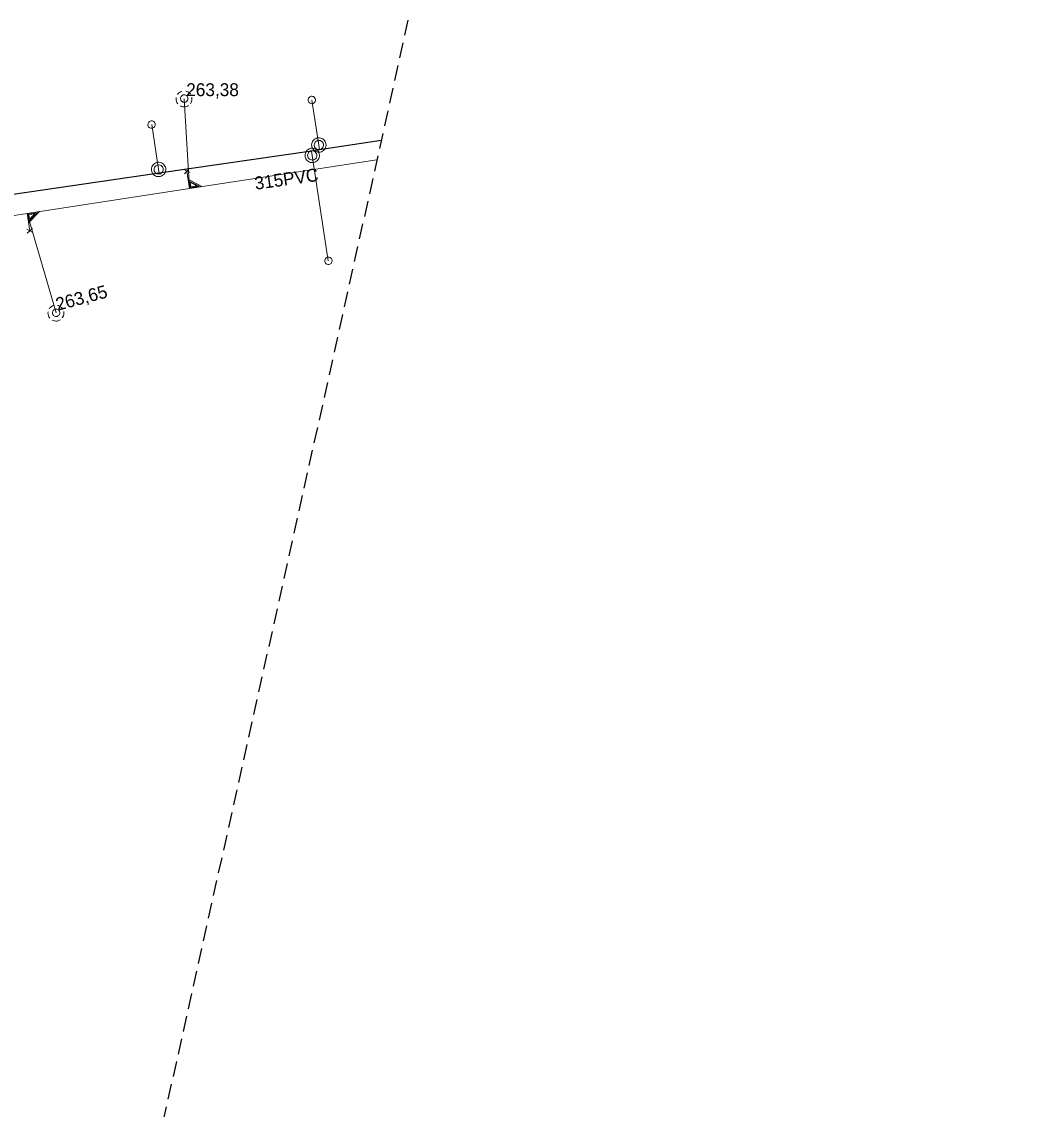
# Model space of a CAD drawing. Extents: x -732096 to -731933, y -1048703 to -1047964.
# Drawn here: x -732030.5 to -731968.4, y -1048368.5 to -1048301 of the extents above; entities that cross this region are included whole.
import ezdxf

# ---------------------------------------------------------------- set-up
doc = ezdxf.new("R2010")
doc.units = 0
doc.header["$LTSCALE"] = 0.32
doc.linetypes.add('MEDIUM_DASHED', pattern=[4.5, 3, -1.5])
doc.layers.add('1', color=7, linetype='Continuous')
for name, color, linetype, lineweight in [('18', 7, 'Continuous', 13), ('20', 7, 'Continuous', 13), ('49', 7, 'Continuous', 13), ('63', 7, 'MEDIUM_DASHED', 25), ('8', 7, 'Continuous', 13)]:
    doc.layers.add(name, color=color, linetype=linetype, lineweight=lineweight)

msp = doc.modelspace()

# ---------------------------------------------------------------- linework, layer by layer
at = {"layer": '18'}
for p, q in [((-732020.474, -1048310.16), (-732020.07, -1048310.345)), ((-732020.141, -1048310.096), (-732020.431, -1048310.413)), ((-732029.851, -1048314.069), (-732030.223, -1048313.854)), ((-732030.186, -1048314.108), (-732029.857, -1048313.811))]:
    msp.add_line(p, q, dxfattribs=at)
for points in [[(-732020.938, -1048305.689), (-732020.943, -1048305.766), (-732020.938, -1048305.843), (-732020.921, -1048305.918), (-732020.892, -1048305.989), (-732020.852, -1048306.055), (-732020.837, -1048306.077)], [(-732020.593, -1048305.297), (-732020.664, -1048305.325), (-732020.73, -1048305.364), (-732020.791, -1048305.412), (-732020.842, -1048305.469), (-732020.865, -1048305.503)], [(-732020.051, -1048305.48), (-732020.102, -1048305.422), (-732020.159, -1048305.372), (-732020.225, -1048305.331), (-732020.296, -1048305.302), (-732020.345, -1048305.288)], [(-732020.056, -1048306.066), (-732020.016, -1048306.001), (-732019.985, -1048305.931), (-732019.965, -1048305.856), (-732019.958, -1048305.78), (-732019.963, -1048305.703), (-732019.968, -1048305.668)], [(-732020.679, -1048306.206), (-732020.61, -1048306.237), (-732020.534, -1048306.256), (-732020.458, -1048306.263), (-732020.382, -1048306.258), (-732020.306, -1048306.241), (-732020.235, -1048306.213), (-732020.174, -1048306.178)], [(-732020.281, -1048310.248), (-732020.114, -1048311.331), (-732019.352, -1048311.214), (-732020.202, -1048310.76)], [(-732020.134, -1048310.869), (-732020.07, -1048311.28), (-732019.512, -1048311.194), (-732020.134, -1048310.868)], [(-732020.074, -1048310.945), (-732020.03, -1048311.232), (-732019.663, -1048311.176), (-732020.076, -1048310.945)], [(-732030.028, -1048313.966), (-732030.195, -1048312.883), (-732029.434, -1048312.766), (-732030.107, -1048313.455)], [(-732030.076, -1048313.329), (-732030.139, -1048312.919), (-732029.579, -1048312.833), (-732030.075, -1048313.331)], [(-732030.042, -1048313.24), (-732030.086, -1048312.952), (-732029.718, -1048312.895), (-732030.043, -1048313.24)], [(-732028.552, -1048318.597), (-732028.623, -1048318.625), (-732028.69, -1048318.664), (-732028.75, -1048318.712), (-732028.801, -1048318.769), (-732028.825, -1048318.803)], [(-732028.011, -1048318.78), (-732028.061, -1048318.722), (-732028.119, -1048318.672), (-732028.184, -1048318.631), (-732028.255, -1048318.602), (-732028.304, -1048318.588)], [(-732028.897, -1048318.989), (-732028.902, -1048319.066), (-732028.897, -1048319.143), (-732028.88, -1048319.218), (-732028.852, -1048319.289), (-732028.811, -1048319.355), (-732028.796, -1048319.377)], [(-732028.016, -1048319.366), (-732027.975, -1048319.301), (-732027.944, -1048319.231), (-732027.924, -1048319.156), (-732027.917, -1048319.08), (-732027.922, -1048319.003), (-732027.928, -1048318.968)], [(-732028.639, -1048319.506), (-732028.569, -1048319.537), (-732028.494, -1048319.556), (-732028.418, -1048319.563), (-732028.341, -1048319.558), (-732028.266, -1048319.541), (-732028.194, -1048319.513), (-732028.134, -1048319.478)]]:
    msp.add_lwpolyline(points, dxfattribs=at)
for points in [[(-732020.208, -1048305.749), (-732020.215, -1048305.697), (-732020.232, -1048305.647), (-732020.261, -1048305.603), (-732020.299, -1048305.566), (-732020.343, -1048305.539), (-732020.394, -1048305.523), (-732020.446, -1048305.518), (-732020.497, -1048305.525), (-732020.546, -1048305.544), (-732020.59, -1048305.574), (-732020.625, -1048305.613), (-732020.652, -1048305.658), (-732020.666, -1048305.709), (-732020.669, -1048305.761), (-732020.661, -1048305.813), (-732020.641, -1048305.861), (-732020.61, -1048305.904), (-732020.571, -1048305.939), (-732020.524, -1048305.963), (-732020.473, -1048305.977), (-732020.421, -1048305.979), (-732020.37, -1048305.969), (-732020.321, -1048305.947), (-732020.279, -1048305.915), (-732020.247, -1048305.875), (-732020.223, -1048305.828), (-732020.21, -1048305.777)], [(-732028.168, -1048319.049), (-732028.174, -1048318.997), (-732028.191, -1048318.947), (-732028.22, -1048318.903), (-732028.258, -1048318.866), (-732028.303, -1048318.839), (-732028.353, -1048318.823), (-732028.405, -1048318.818), (-732028.456, -1048318.825), (-732028.505, -1048318.844), (-732028.549, -1048318.874), (-732028.585, -1048318.913), (-732028.611, -1048318.958), (-732028.625, -1048319.009), (-732028.629, -1048319.061), (-732028.62, -1048319.113), (-732028.6, -1048319.161), (-732028.57, -1048319.204), (-732028.53, -1048319.239), (-732028.483, -1048319.263), (-732028.433, -1048319.277), (-732028.38, -1048319.279), (-732028.329, -1048319.269), (-732028.281, -1048319.247), (-732028.239, -1048319.215), (-732028.206, -1048319.175), (-732028.182, -1048319.128), (-732028.169, -1048319.077)]]:
    msp.add_lwpolyline(points, close=True, dxfattribs=at)
at = {"layer": '20'}
msp.add_lwpolyline([(-732034.51, -1048313.55), (-732033.17, -1048313.344), (-732030.204, -1048312.887), (-732020.123, -1048311.336), (-732008.47, -1048309.542)], dxfattribs=at)
msp.add_lwpolyline([(-732034.51, -1048313.55), (-732033.17, -1048313.344), (-732030.204, -1048312.887), (-732020.123, -1048311.336), (-732008.47, -1048309.542)], dxfattribs=at)
at = {"layer": '49'}
for p, q in [((-732020.44, -1048305.76), (-732020.123, -1048311.336)), ((-732020.44, -1048305.76), (-732020.123, -1048311.336)), ((-732028.399, -1048319.06), (-732030.204, -1048312.887)), ((-732028.399, -1048319.06), (-732030.204, -1048312.887))]:
    msp.add_line(p, q, dxfattribs=at)
at = {"layer": '63'}
msp.add_lwpolyline([(-731968.389, -1048129.392), (-732027.835, -1048396.578)], dxfattribs=at)
at = {"layer": '8'}
for p, q in [((-732012.079, -1048308.64), (-732012.51, -1048305.837)), ((-732022.03, -1048310.16), (-732022.458, -1048307.363)), ((-732012.035, -1048308.931), (-732012.079, -1048308.64)), ((-732012.542, -1048309.009), (-732012.5, -1048309.28)), ((-732012.5, -1048309.28), (-732011.497, -1048315.826)), ((-732021.995, -1048310.381), (-732022.03, -1048310.16))]:
    msp.add_line(p, q, dxfattribs=at)
for points in [[(-732012.551, -1048305.608), (-732012.602, -1048305.622), (-732012.649, -1048305.647), (-732012.688, -1048305.681), (-732012.719, -1048305.724), (-732012.74, -1048305.772), (-732012.748, -1048305.824), (-732012.746, -1048305.876), (-732012.731, -1048305.927), (-732012.705, -1048305.972), (-732012.669, -1048306.012), (-732012.626, -1048306.041), (-732012.577, -1048306.06), (-732012.525, -1048306.067), (-732012.473, -1048306.063), (-732012.423, -1048306.047), (-732012.378, -1048306.02), (-732012.34, -1048305.984), (-732012.311, -1048305.939), (-732012.294, -1048305.89), (-732012.287, -1048305.838), (-732012.293, -1048305.786), (-732012.31, -1048305.736), (-732012.339, -1048305.692), (-732012.377, -1048305.655), (-732012.421, -1048305.628), (-732012.471, -1048305.611), (-732012.523, -1048305.606)], [(-732022.501, -1048307.136), (-732022.552, -1048307.149), (-732022.599, -1048307.175), (-732022.638, -1048307.209), (-732022.669, -1048307.252), (-732022.689, -1048307.3), (-732022.697, -1048307.352), (-732022.694, -1048307.404), (-732022.68, -1048307.455), (-732022.654, -1048307.5), (-732022.617, -1048307.539), (-732022.574, -1048307.568), (-732022.525, -1048307.587), (-732022.473, -1048307.594), (-732022.421, -1048307.59), (-732022.371, -1048307.574), (-732022.326, -1048307.546), (-732022.288, -1048307.51), (-732022.26, -1048307.465), (-732022.243, -1048307.416), (-732022.236, -1048307.364), (-732022.242, -1048307.312), (-732022.26, -1048307.262), (-732022.289, -1048307.218), (-732022.327, -1048307.181), (-732022.371, -1048307.154), (-732022.421, -1048307.138), (-732022.473, -1048307.133)], [(-732011.632, -1048308.629), (-732011.638, -1048308.556), (-732011.656, -1048308.485), (-732011.685, -1048308.418), (-732011.725, -1048308.357), (-732011.774, -1048308.302), (-732011.831, -1048308.257), (-732011.895, -1048308.222), (-732011.964, -1048308.197), (-732012.036, -1048308.184), (-732012.11, -1048308.183), (-732012.182, -1048308.194), (-732012.252, -1048308.217), (-732012.316, -1048308.25), (-732012.375, -1048308.294), (-732012.426, -1048308.347), (-732012.467, -1048308.407), (-732012.498, -1048308.474), (-732012.518, -1048308.544), (-732012.526, -1048308.617), (-732012.522, -1048308.69), (-732012.506, -1048308.761), (-732012.479, -1048308.829), (-732012.441, -1048308.892), (-732012.393, -1048308.947), (-732012.337, -1048308.994), (-732012.274, -1048309.031), (-732012.206, -1048309.058), (-732012.134, -1048309.073), (-732012.061, -1048309.076), (-732011.988, -1048309.067), (-732011.918, -1048309.046), (-732011.852, -1048309.014), (-732011.792, -1048308.972), (-732011.74, -1048308.921), (-732011.697, -1048308.861), (-732011.664, -1048308.796), (-732011.643, -1048308.726), (-732011.633, -1048308.654)], [(-732011.793, -1048308.629), (-732011.799, -1048308.571), (-732011.817, -1048308.515), (-732011.845, -1048308.464), (-732011.884, -1048308.42), (-732011.93, -1048308.384), (-732011.983, -1048308.359), (-732012.04, -1048308.345), (-732012.099, -1048308.343), (-732012.156, -1048308.353), (-732012.211, -1048308.375), (-732012.26, -1048308.407), (-732012.301, -1048308.448), (-732012.333, -1048308.497), (-732012.355, -1048308.552), (-732012.365, -1048308.609), (-732012.363, -1048308.668), (-732012.349, -1048308.725), (-732012.324, -1048308.778), (-732012.288, -1048308.824), (-732012.244, -1048308.863), (-732012.193, -1048308.891), (-732012.137, -1048308.909), (-732012.079, -1048308.915), (-732012.021, -1048308.909), (-732011.965, -1048308.892), (-732011.914, -1048308.863), (-732011.87, -1048308.824), (-732011.835, -1048308.778), (-732011.81, -1048308.725), (-732011.796, -1048308.668)], [(-732012.423, -1048309.719), (-732012.352, -1048309.702), (-732012.284, -1048309.674), (-732012.223, -1048309.635), (-732012.168, -1048309.586), (-732012.121, -1048309.53), (-732012.085, -1048309.466), (-732012.06, -1048309.398), (-732012.046, -1048309.326), (-732012.044, -1048309.253), (-732012.054, -1048309.18), (-732012.075, -1048309.11), (-732012.109, -1048309.044), (-732012.151, -1048308.986), (-732012.203, -1048308.934), (-732012.263, -1048308.892), (-732012.329, -1048308.86), (-732012.4, -1048308.839), (-732012.472, -1048308.83), (-732012.545, -1048308.833), (-732012.617, -1048308.848), (-732012.685, -1048308.874), (-732012.748, -1048308.911), (-732012.804, -1048308.958), (-732012.852, -1048309.014), (-732012.89, -1048309.076), (-732012.917, -1048309.144), (-732012.933, -1048309.216), (-732012.937, -1048309.289), (-732012.929, -1048309.362), (-732012.91, -1048309.432), (-732012.878, -1048309.498), (-732012.837, -1048309.559), (-732012.786, -1048309.612), (-732012.728, -1048309.656), (-732012.662, -1048309.689), (-732012.593, -1048309.712), (-732012.521, -1048309.723), (-732012.448, -1048309.722)], [(-732012.447, -1048309.56), (-732012.391, -1048309.545), (-732012.338, -1048309.519), (-732012.292, -1048309.484), (-732012.254, -1048309.438), (-732012.226, -1048309.388), (-732012.209, -1048309.331), (-732012.203, -1048309.273), (-732012.21, -1048309.214), (-732012.229, -1048309.16), (-732012.259, -1048309.108), (-732012.298, -1048309.065), (-732012.344, -1048309.03), (-732012.398, -1048309.006), (-732012.455, -1048308.993), (-732012.513, -1048308.991), (-732012.571, -1048309.002), (-732012.625, -1048309.024), (-732012.674, -1048309.057), (-732012.714, -1048309.099), (-732012.746, -1048309.149), (-732012.766, -1048309.203), (-732012.776, -1048309.261), (-732012.773, -1048309.32), (-732012.758, -1048309.376), (-732012.733, -1048309.429), (-732012.697, -1048309.475), (-732012.652, -1048309.513), (-732012.601, -1048309.54), (-732012.545, -1048309.557), (-732012.486, -1048309.563)], [(-732021.583, -1048310.149), (-732021.589, -1048310.076), (-732021.607, -1048310.005), (-732021.636, -1048309.938), (-732021.676, -1048309.877), (-732021.725, -1048309.822), (-732021.782, -1048309.777), (-732021.846, -1048309.742), (-732021.915, -1048309.717), (-732021.987, -1048309.704), (-732022.061, -1048309.703), (-732022.133, -1048309.714), (-732022.203, -1048309.737), (-732022.267, -1048309.77), (-732022.326, -1048309.814), (-732022.377, -1048309.867), (-732022.418, -1048309.927), (-732022.449, -1048309.994), (-732022.469, -1048310.064), (-732022.477, -1048310.137), (-732022.473, -1048310.21), (-732022.457, -1048310.281), (-732022.43, -1048310.349), (-732022.392, -1048310.412), (-732022.344, -1048310.467), (-732022.288, -1048310.514), (-732022.225, -1048310.551), (-732022.157, -1048310.578), (-732022.085, -1048310.593), (-732022.012, -1048310.596), (-732021.939, -1048310.587), (-732021.869, -1048310.566), (-732021.803, -1048310.534), (-732021.743, -1048310.492), (-732021.691, -1048310.441), (-732021.648, -1048310.381), (-732021.615, -1048310.316), (-732021.594, -1048310.246), (-732021.584, -1048310.174)], [(-732021.744, -1048310.149), (-732021.75, -1048310.091), (-732021.768, -1048310.035), (-732021.796, -1048309.984), (-732021.835, -1048309.94), (-732021.881, -1048309.904), (-732021.934, -1048309.879), (-732021.991, -1048309.865), (-732022.05, -1048309.863), (-732022.107, -1048309.873), (-732022.162, -1048309.895), (-732022.211, -1048309.927), (-732022.252, -1048309.968), (-732022.284, -1048310.017), (-732022.306, -1048310.072), (-732022.316, -1048310.129), (-732022.314, -1048310.188), (-732022.3, -1048310.245), (-732022.275, -1048310.298), (-732022.239, -1048310.344), (-732022.195, -1048310.383), (-732022.144, -1048310.411), (-732022.088, -1048310.429), (-732022.03, -1048310.435), (-732021.972, -1048310.429), (-732021.916, -1048310.412), (-732021.865, -1048310.383), (-732021.821, -1048310.344), (-732021.786, -1048310.298), (-732021.761, -1048310.245), (-732021.747, -1048310.188)], [(-732011.451, -1048316.052), (-732011.401, -1048316.038), (-732011.354, -1048316.013), (-732011.315, -1048315.979), (-732011.284, -1048315.936), (-732011.264, -1048315.887), (-732011.256, -1048315.835), (-732011.259, -1048315.783), (-732011.274, -1048315.733), (-732011.3, -1048315.687), (-732011.336, -1048315.648), (-732011.38, -1048315.619), (-732011.428, -1048315.601), (-732011.481, -1048315.593), (-732011.533, -1048315.598), (-732011.583, -1048315.614), (-732011.627, -1048315.642), (-732011.665, -1048315.678), (-732011.694, -1048315.723), (-732011.711, -1048315.772), (-732011.717, -1048315.825), (-732011.711, -1048315.877), (-732011.693, -1048315.926), (-732011.664, -1048315.971), (-732011.626, -1048316.007), (-732011.581, -1048316.034), (-732011.531, -1048316.05), (-732011.479, -1048316.055)]]:
    msp.add_lwpolyline(points, close=True, dxfattribs=at)
at = {"layer": '8', "lineweight": 25}
msp.add_lwpolyline([(-732008.203, -1048308.341), (-732012.035, -1048308.931), (-732012.542, -1048309.009), (-732021.995, -1048310.381), (-732032.087, -1048311.846), (-732032.699, -1048311.93)], dxfattribs=at)

# ---------------------------------------------------------------- texts
at = {"layer": '1'}
msp.add_text('263,38', height=0.8, dxfattribs=at).set_placement((-732020.318, -1048305.597))
for s, rotation, p in [('315PVC', 8, (-732016.011, -1048311.412)), ('263,65', 15, (-732028.304, -1048318.927))]:
    msp.add_text(s, height=0.8, rotation=rotation, dxfattribs=at).set_placement(p)

doc.saveas('drawing.dxf')
